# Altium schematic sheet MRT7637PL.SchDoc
size A3
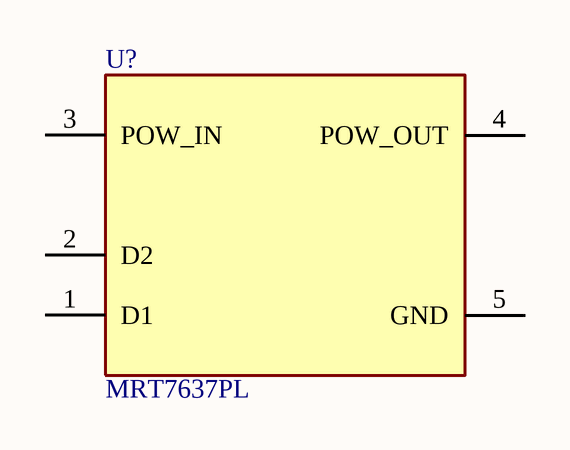
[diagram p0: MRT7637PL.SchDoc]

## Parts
U?  MRT7637PL

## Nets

Not connected (* = marked no-connect by the designer): U? 1(D1) 2(D2) 3(POW_IN) 4(POW_OUT) 5(GND)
